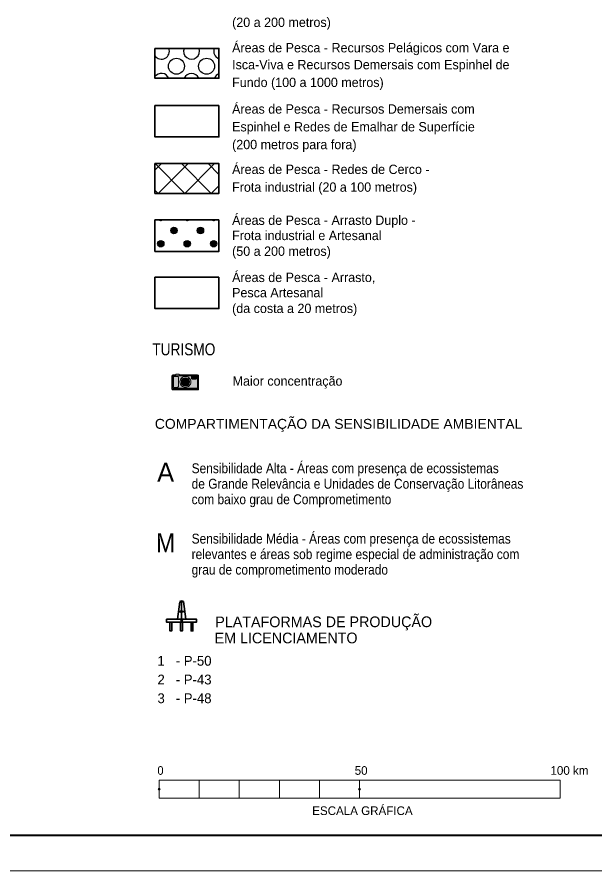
# Model space of a CAD drawing. Extents: x -6.3 to 58.7, y 19.8 to 60.6.
# Drawn here: x 31.28 to 44.83, y 19.82 to 39.84 of the extents above; entities that cross this region are included whole.
import ezdxf
from ezdxf.enums import TextEntityAlignment as Align

# ---------------------------------------------------------------- set-up
doc = ezdxf.new("R2010")
doc.units = 0
doc.header["$LTSCALE"] = 0.092
doc.header["$PDMODE"] = 32
doc.header["$PDSIZE"] = 0.046
for name, color, linetype, lineweight in [('2', 7, 'Continuous', 35), ('58', 7, 'Continuous', 13), ('60', 7, 'Continuous', 40), ('63', 7, 'Continuous', 13)]:
    doc.layers.add(name, color=color, linetype=linetype, lineweight=lineweight)

msp = doc.modelspace()

# ---------------------------------------------------------------- hatches: boundary and pattern name
at = {"layer": '58'}
for points in [[(35.00929, 34.89139, 1), (34.90368, 34.78578, 1)], [(35.63053, 34.89139, 1), (35.52492, 34.78578, 1)], [(34.69867, 34.58077, 1), (34.59305, 34.47515, 1)], [(35.31991, 34.58077, 1), (35.2143, 34.47515, 1)], [(35.94115, 34.58077, 1), (35.83554, 34.47515, 1)], [(34.93273, 31.45081), (34.91305, 31.44419), (34.90644, 31.42451), (34.90644, 31.1257), (34.91305, 31.10486), (34.93273, 31.09797), (35.508, 31.09797), (35.52785, 31.10486), (35.53447, 31.1257), (35.53447, 31.42451), (35.53107, 31.44124), (35.5207, 31.44848), (35.508, 31.45081), (35.07744, 31.45081), (35.07744, 31.46869), (35.00321, 31.46869), (35.00321, 31.45081)], [(34.93273, 31.43229), (35.508, 31.43229), (35.508, 31.14189), (34.93273, 31.14189)], [(34.98192, 31.417), (34.96529, 31.41566), (34.95348, 31.41109), (34.94633, 31.40367), (34.94418, 31.39312), (34.94418, 31.17838), (34.95348, 31.16237), (34.98192, 31.157), (35.02306, 31.157), (35.05025, 31.16237), (35.05955, 31.17838), (35.05955, 31.39312), (35.05705, 31.40367), (35.05025, 31.41109), (35.0388, 31.41566), (35.02306, 31.417)], [(35.22412, 31.41583), (35.19872, 31.41342), (35.17529, 31.40627), (35.15382, 31.39446), (35.13432, 31.378), (35.11805, 31.35806), (35.10642, 31.33623), (35.09944, 31.31235), (35.0973, 31.28642), (35.10642, 31.23803), (35.13432, 31.19644), (35.15382, 31.17972), (35.17529, 31.16791), (35.19872, 31.16058), (35.22412, 31.15834), (35.24934, 31.16058), (35.27295, 31.16791), (35.2946, 31.17972), (35.31445, 31.19644), (35.33091, 31.2163), (35.3429, 31.23803), (35.34987, 31.26137), (35.3522, 31.28642), (35.34987, 31.31235), (35.3429, 31.33623), (35.33091, 31.35806), (35.31445, 31.378), (35.2946, 31.39446), (35.27295, 31.40627), (35.24934, 31.41342)], [(35.22412, 31.38578), (35.26097, 31.37845), (35.29281, 31.35636), (35.31481, 31.32416), (35.32232, 31.28642), (35.31481, 31.24885), (35.29281, 31.2171), (35.26097, 31.19555), (35.22412, 31.18839), (35.18799, 31.19555), (35.15704, 31.2171), (35.13558, 31.24885), (35.1286, 31.28642), (35.13558, 31.32416), (35.15704, 31.35636), (35.18799, 31.37845)], [(35.22412, 31.37049), (35.19318, 31.36441), (35.16652, 31.34625), (35.14846, 31.31915), (35.14237, 31.28642), (35.14846, 31.25494), (35.16652, 31.22873), (35.19318, 31.21084), (35.22412, 31.20503), (35.25525, 31.21084), (35.28172, 31.22873), (35.29961, 31.25494), (35.30569, 31.28642), (35.29961, 31.31915), (35.28172, 31.34625), (35.25525, 31.36441)], [(35.38493, 31.417), (35.36955, 31.41199), (35.36472, 31.39687), (35.36472, 31.37049), (35.36955, 31.35564), (35.38493, 31.35072), (35.469, 31.35072), (35.48403, 31.35564), (35.48904, 31.37049), (35.48904, 31.39687), (35.48403, 31.41199), (35.469, 31.417)], [(35.38744, 31.41199), (35.46525, 31.41199), (35.4783, 31.40796), (35.48278, 31.3958), (35.48278, 31.37049), (35.4783, 31.35913), (35.46525, 31.35537), (35.38744, 31.35537), (35.3742, 31.35913), (35.36973, 31.37049), (35.36973, 31.3958), (35.3742, 31.40796)], [(34.94275, 31.13437), (35.49923, 31.13437), (35.50585, 31.13214), (35.508, 31.1257), (35.50585, 31.11809), (35.49923, 31.11559), (34.94275, 31.11559), (34.93506, 31.11809), (34.93273, 31.1257), (34.93506, 31.13214)]]:
    msp.add_hatch(color=256, dxfattribs=at).paths.add_polyline_path(points)

# ---------------------------------------------------------------- linework, layer by layer
at = {"layer": '2'}
for p, q in [((34.6835, 35.0847), (34.60822, 35.0847)), ((35.30475, 35.0847), (35.22946, 35.0847)), ((35.92599, 35.0847), (35.8507, 35.0847))]:
    msp.add_line(p, q, dxfattribs=at)
for centre in [(34.64586, 35.1492), (35.2671, 35.1492), (35.88835, 35.1492)]:
    msp.add_arc(centre, 0.07468, 239.7311, 300.26891, dxfattribs=at)
at = {"layer": '58', "lineweight": 25}
for p, q in [((34.66454, 36.40699), (34.51012, 36.25257)), ((35.20992, 35.70967), (34.51261, 36.40699)), ((35.28578, 36.40699), (34.58847, 35.70967)), ((35.83117, 35.70967), (35.13385, 36.40699)), ((35.90703, 36.40699), (35.20971, 35.70967)), ((36.00994, 36.15214), (35.75509, 36.40699)), ((36.00994, 35.88866), (35.83096, 35.70967)), ((34.58868, 35.70967), (34.51012, 35.78823))]:
    msp.add_line(p, q, dxfattribs=at)
at = {"layer": '58', "lineweight": 35}
for p, q in [((35.03573, 25.72397), (35.09279, 26.13234)), ((35.13465, 26.11714), (35.09279, 26.13234)), ((35.13465, 26.15327), (35.09368, 26.13726)), ((35.13465, 26.15327), (35.17758, 26.13646)), ((35.13465, 26.11714), (35.17829, 26.13315)), ((35.13465, 25.72397), (35.13465, 26.11714)), ((35.23375, 25.72397), (35.17829, 26.13315)), ((35.13465, 25.92011), (35.05934, 25.89086)), ((35.13465, 25.88245), (35.06167, 25.91009)), ((35.13465, 25.9185), (35.21103, 25.88997)), ((35.13465, 25.88496), (35.20852, 25.91259))]:
    msp.add_line(p, q, dxfattribs=at)
for points in [[(34.51001, 39.10814), (36.00983, 39.10814), (36.00983, 38.41083), (34.51001, 38.41083)], [(36.00988, 37.767), (34.51007, 37.767), (34.51007, 37.03196), (36.00988, 37.03196)], [(34.51012, 36.40699), (36.00994, 36.40699), (36.00994, 35.70967), (34.51012, 35.70967)], [(36.00998, 35.0847), (34.51018, 35.0847), (34.51018, 34.34967), (36.00998, 34.34967)], [(36.01004, 33.74356), (34.51023, 33.74356), (34.51023, 33.00852), (36.01004, 33.00852)], [(34.78333, 25.72397), (35.48274, 25.72397), (35.48274, 25.65099), (34.78333, 25.65099)], [(34.86222, 25.65099), (34.90497, 25.65099), (34.90497, 25.44725), (34.86222, 25.44725)], [(35.11121, 25.65099), (35.15397, 25.65099), (35.15397, 25.44725), (35.11121, 25.44725)], [(35.35771, 25.65099), (35.40064, 25.65099), (35.40064, 25.44725), (35.35771, 25.44725)]]:
    msp.add_lwpolyline(points, close=True, dxfattribs=at)
at = {"layer": '58'}
for points in [[(34.93273, 31.45081), (34.91305, 31.44419), (34.90644, 31.42451), (34.90644, 31.1257), (34.91305, 31.10486), (34.93273, 31.09797), (35.508, 31.09797), (35.52785, 31.10486), (35.53447, 31.1257), (35.53447, 31.42451), (35.53107, 31.44124), (35.5207, 31.44848), (35.508, 31.45081), (35.07744, 31.45081), (35.07744, 31.46869), (35.00321, 31.46869), (35.00321, 31.45081)], [(34.93273, 31.43229), (35.508, 31.43229), (35.508, 31.14189), (34.93273, 31.14189)], [(34.98192, 31.417), (34.96529, 31.41566), (34.95348, 31.41109), (34.94633, 31.40367), (34.94418, 31.39312), (34.94418, 31.17838), (34.95348, 31.16237), (34.98192, 31.157), (35.02306, 31.157), (35.05025, 31.16237), (35.05955, 31.17838), (35.05955, 31.39312), (35.05705, 31.40367), (35.05025, 31.41109), (35.0388, 31.41566), (35.02306, 31.417)], [(35.22412, 31.41583), (35.19872, 31.41342), (35.17529, 31.40627), (35.15382, 31.39446), (35.13432, 31.378), (35.11805, 31.35806), (35.10642, 31.33623), (35.09944, 31.31235), (35.0973, 31.28642), (35.10642, 31.23803), (35.13432, 31.19644), (35.15382, 31.17972), (35.17529, 31.16791), (35.19872, 31.16058), (35.22412, 31.15834), (35.24934, 31.16058), (35.27295, 31.16791), (35.2946, 31.17972), (35.31445, 31.19644), (35.33091, 31.2163), (35.3429, 31.23803), (35.34987, 31.26137), (35.3522, 31.28642), (35.34987, 31.31235), (35.3429, 31.33623), (35.33091, 31.35806), (35.31445, 31.378), (35.2946, 31.39446), (35.27295, 31.40627), (35.24934, 31.41342)], [(35.22412, 31.38578), (35.26097, 31.37845), (35.29281, 31.35636), (35.31481, 31.32416), (35.32232, 31.28642), (35.31481, 31.24885), (35.29281, 31.2171), (35.26097, 31.19555), (35.22412, 31.18839), (35.18799, 31.19555), (35.15704, 31.2171), (35.13558, 31.24885), (35.1286, 31.28642), (35.13558, 31.32416), (35.15704, 31.35636), (35.18799, 31.37845)], [(35.22412, 31.37049), (35.19318, 31.36441), (35.16652, 31.34625), (35.14846, 31.31915), (35.14237, 31.28642), (35.14846, 31.25494), (35.16652, 31.22873), (35.19318, 31.21084), (35.22412, 31.20503), (35.25525, 31.21084), (35.28172, 31.22873), (35.29961, 31.25494), (35.30569, 31.28642), (35.29961, 31.31915), (35.28172, 31.34625), (35.25525, 31.36441)], [(35.38493, 31.417), (35.36955, 31.41199), (35.36472, 31.39687), (35.36472, 31.37049), (35.36955, 31.35564), (35.38493, 31.35072), (35.469, 31.35072), (35.48403, 31.35564), (35.48904, 31.37049), (35.48904, 31.39687), (35.48403, 31.41199), (35.469, 31.417)], [(35.38744, 31.41199), (35.46525, 31.41199), (35.4783, 31.40796), (35.48278, 31.3958), (35.48278, 31.37049), (35.4783, 31.35913), (35.46525, 31.35537), (35.38744, 31.35537), (35.3742, 31.35913), (35.36973, 31.37049), (35.36973, 31.3958), (35.3742, 31.40796)], [(34.94275, 31.13437), (35.49923, 31.13437), (35.50585, 31.13214), (35.508, 31.1257), (35.50585, 31.11809), (35.49923, 31.11559), (34.94275, 31.11559), (34.93506, 31.11809), (34.93273, 31.1257), (34.93506, 31.13214)], [(34.60597, 21.94456), (44.01201, 21.94456), (44.01201, 21.5236), (34.60597, 21.5236)], [(34.60597, 21.94456), (35.54657, 21.94456), (35.54657, 21.5236), (34.60597, 21.5236)], [(36.48717, 21.94456), (37.42778, 21.94456), (37.42778, 21.5236), (36.48717, 21.5236)], [(38.36838, 21.94456), (39.30899, 21.94456), (39.30899, 21.5236), (38.36838, 21.5236)]]:
    msp.add_lwpolyline(points, close=True, dxfattribs=at)
at = {"layer": '58', "lineweight": 25}
for centre, radius in [((35.0146, 38.69038), 0.1875), ((35.72171, 38.69038), 0.1875), ((34.95648, 34.83858), 0.07468), ((35.57772, 34.83858), 0.07468), ((34.64586, 34.52796), 0.07468), ((35.2671, 34.52796), 0.07468), ((35.88835, 34.52796), 0.07468)]:
    msp.add_circle(centre, radius, dxfattribs=at)
for centre, radius, start, end in [((34.66105, 39.04393), 0.1875, 216.33952, 20.02563), ((35.36816, 39.04393), 0.1875, 159.97436, 20.02564), ((36.07526, 39.04393), 0.1875, 159.97436, 249.57581), ((34.66105, 38.33683), 0.1875, 23.24535, 143.66047), ((35.36816, 38.33683), 0.1875, 23.24536, 156.75465), ((36.07526, 38.33683), 0.1875, 110.42419, 156.75464), ((34.64586, 35.1492), 0.07468, 239.7311, 300.26891), ((35.2671, 35.1492), 0.07468, 239.7311, 300.26891), ((35.88835, 35.1492), 0.07468, 239.7311, 300.26891)]:
    msp.add_arc(centre, radius, start, end, dxfattribs=at)
at = {"layer": '58'}
for p in [(35.13214, 25.69123), (35.14055, 25.69374), (34.60597, 21.73408), (39.30899, 21.73408)]:
    msp.add_point(p, dxfattribs=at)
at = {"layer": '60'}
msp.add_lwpolyline([(-3.73781, 29.96257), (-3.73781, 20.65308), (57.84015, 20.65308), (57.84016, 59.74412), (-3.73781, 59.74412), (-3.73781, 40.1986), (-3.73781, 40.1986)], dxfattribs=at)
at = {"layer": '63'}
msp.add_lwpolyline([(-6.28685, 19.8174), (58.67584, 19.8174), (58.67584, 60.5798), (-6.28685, 60.5798)], close=True, dxfattribs=at)

# ---------------------------------------------------------------- texts
at = {"layer": '58'}
for s, height, p in [('(20 a 200 metros)', 0.2194, (36.31943, 39.61215)), ('Áreas de Pesca - Recursos Pelágicos com Vara e ', 0.2194, (36.31934, 39.01596)), ('Isca-Viva e Recursos Demersais com Espinhel de', 0.2194, (36.31934, 38.61948)), ('Fundo (100 a 1000 metros)', 0.2194, (36.31934, 38.20287)), ('Áreas de Pesca - Recursos Demersais com', 0.2194, (36.31925, 37.57877)), ('Espinhel e Redes de Emalhar de Superfície ', 0.2194, (36.31925, 37.16217)), ('(200 metros para fora)', 0.2194, (36.31925, 36.74556)), ('Áreas de Pesca - Redes de Cerco -', 0.2194, (36.3193, 36.16393)), ('Frota industrial (20 a 100 metros)', 0.2194, (36.3193, 35.74732)), ('Áreas de Pesca - Arrasto Duplo -', 0.2194, (36.31936, 34.97043)), ('Frota industrial e Artesanal', 0.2194, (36.31936, 34.61289)), ('(50 a 200 metros)', 0.2194, (36.31936, 34.24376)), ('Áreas de Pesca - Arrasto,', 0.2194, (36.31941, 33.62929)), ('Pesca Artesanal', 0.2194, (36.31941, 33.27174)), ('(da costa a 20 metros)', 0.2194, (36.31941, 32.90262)), ('Maior concentração', 0.2194, (36.3308, 31.19881)), ('1   - P-50', 0.2306, (34.56884, 24.63053)), ('2   - P-43', 0.2306, (34.56884, 24.19124)), ('3   - P-48', 0.2306, (34.56884, 23.75196)), ('50', 0.2032, (39.19492, 22.07174)), ('100 km', 0.2032, (43.78626, 22.07174)), ('ESCALA GRÁFICA', 0.2032, (38.19835, 21.12833))]:
    msp.add_text(s, height=height, dxfattribs=at).set_placement(p)
for s, height, width, p in [('TURISMO', 0.2822, 0.85, (34.44782, 31.91056)), ('COMPARTIMENTAÇÃO DA SENSIBILIDADE AMBIENTAL', 0.2326, 1.05, (34.50666, 30.18694)), ('Sensibilidade Alta - Áreas com presença de ecossistemas', 0.2326, 0.9, (35.37012, 29.14566)), ('de Grande Relevância e Unidades de Conservação Litorâneas', 0.2326, 0.9, (35.37012, 28.78208)), ('com baixo grau de Comprometimento', 0.2326, 0.9, (35.37012, 28.4185)), ('Sensibilidade Média - Áreas com presença de ecossistemas', 0.2326, 0.9, (35.37012, 27.49488)), ('relevantes e áreas sob regime especial de administração com', 0.2326, 0.9, (35.37012, 27.1313)), ('grau de comprometimento moderado', 0.2326, 0.9, (35.37012, 26.76771)), ('0', 0.2032, 0.95, (34.56798, 22.07174))]:
    msp.add_text(s, height=height, dxfattribs=dict(at, width=width)).set_placement(p)
msp.add_text('A', height=0.4457, dxfattribs=at).set_placement((34.76033, 28.94431), align=Align.CENTER)
at = {"layer": '58', "width": 0.9}
msp.add_text('M', height=0.4457, dxfattribs=at).set_placement((34.75937, 27.29352), align=Align.CENTER)
at = {"layer": '58'}
for s, p in [('PLATAFORMAS DE PRODUÇÃO', (38.46783, 25.53437)), ('EM LICENCIAMENTO', (37.58521, 25.15561))]:
    msp.add_text(s, height=0.2507, rotation=0.028, dxfattribs=at).set_placement(p, align=Align.CENTER)

doc.saveas('drawing.dxf')
